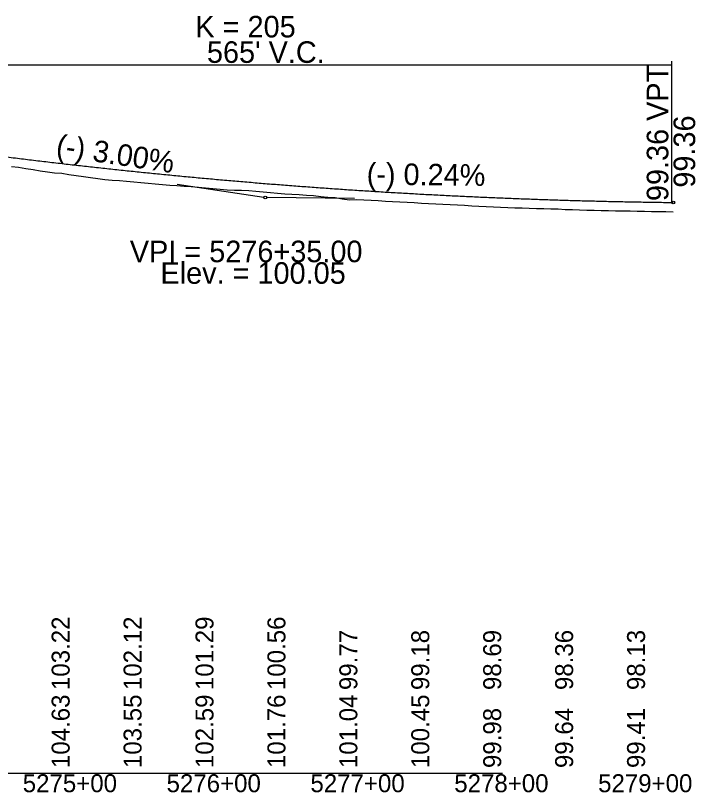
# Model space of a CAD drawing. Extents: x 2121671 to 2169879, y 557274 to 599957.
# Drawn here: x 2157029 to 2157502, y 579173 to 579714 of the extents above; entities that cross this region are included whole.
import ezdxf

# ---------------------------------------------------------------- set-up
doc = ezdxf.new("R2010")
doc.units = 0
for name, color, linetype in [('RD_DDB_GradeTX', 7, 'Continuous'), ('RD_DDB_Profile_EX', 7, 'Continuous'), ('RD_DDB_Profile_Lbl', 7, 'Continuous'), ('RD_DDB_Profile_PR', 7, 'Continuous'), ('RD_DDB_StaTX', 7, 'Continuous'), ('RD_DDB_StripGrade', 7, 'Continuous'), ('RD_DDB_VCLbl', 7, 'Continuous'), ('RD_GPK_Profile_Cell', 7, 'Continuous')]:
    doc.layers.add(name, color=color, linetype=linetype)

msp = doc.modelspace()

# ---------------------------------------------------------------- linework, layer by layer
at = {"layer": 'RD_DDB_GradeTX'}
for p, q in [((2157141.62, 579596.26), (2157201.95, 579587.21)), ((2157264.93, 579586.31), (2157203.93, 579587.05))]:
    msp.add_line(p, q, dxfattribs=at)
for centre in [(2157202.93, 579587.07), (2157486.53, 579583.63)]:
    msp.add_circle(centre, 1, dxfattribs=at)
at = {"layer": 'RD_DDB_Profile_EX'}
for points in [[(2157026.48, 579608.66), (2157031.48, 579608.07), (2157036.48, 579607.26), (2157041.48, 579606.45), (2157046.48, 579605.6), (2157051.48, 579604.83), (2157056.48, 579604.33), (2157061.48, 579603.98), (2157066.48, 579603.12), (2157071.48, 579602.4), (2157076.48, 579601.69), (2157081.48, 579600.99), (2157086.48, 579600.28), (2157091.48, 579599.61), (2157096.48, 579599.22), (2157101.48, 579598.99), (2157106.48, 579598.51), (2157111.48, 579598.06), (2157116.48, 579597.54), (2157121.48, 579597.08), (2157126.48, 579596.62), (2157131.48, 579596.16), (2157136.48, 579595.75), (2157141.48, 579595.36), (2157146.48, 579595), (2157151.48, 579594.65), (2157156.48, 579594.2), (2157161.48, 579593.83), (2157166.48, 579593.4), (2157171.48, 579592.92), (2157176.48, 579592.42), (2157181.48, 579592.07), (2157186.48, 579592.1), (2157191.48, 579591.86), (2157196.48, 579591.4), (2157201.48, 579590.95), (2157206.48, 579590.5), (2157211.48, 579589.99), (2157216.48, 579589.7), (2157221.48, 579589.45)], [(2157221.48, 579589.45), (2157226.48, 579589.11), (2157231.48, 579588.68), (2157236.48, 579588.39), (2157241.48, 579587.88), (2157246.48, 579587.4), (2157251.48, 579586.96), (2157256.48, 579586.09), (2157261.48, 579585.55), (2157266.48, 579585.73), (2157271.48, 579585.51), (2157276.48, 579585.19), (2157281.48, 579584.88), (2157286.48, 579584.59), (2157291.48, 579584.34), (2157296.48, 579584.11), (2157301.48, 579583.86), (2157306.48, 579583.59), (2157311.48, 579583.16), (2157316.48, 579582.81), (2157321.48, 579582.57), (2157326.48, 579582.41), (2157331.48, 579582.23), (2157336.48, 579582.02), (2157341.48, 579581.7), (2157346.48, 579581.33), (2157351.48, 579581.09), (2157356.48, 579580.86), (2157361.48, 579580.61), (2157366.48, 579580.35), (2157371.48, 579580.09), (2157376.48, 579579.95), (2157381.48, 579579.85), (2157386.48, 579579.57), (2157391.48, 579579.47), (2157396.48, 579579.35), (2157401.48, 579579.23), (2157406.48, 579579.11), (2157411.48, 579578.84), (2157416.48, 579578.69), (2157421.48, 579578.47), (2157426.48, 579578.27), (2157431.48, 579578.27), (2157436.48, 579578.15), (2157441.48, 579577.99), (2157446.48, 579577.84), (2157451.48, 579577.73), (2157456.48, 579577.74), (2157461.48, 579577.62), (2157466.48, 579577.51), (2157471.48, 579577.4), (2157476.48, 579577.3), (2157481.48, 579577.26), (2157486.53, 579577.21)]]:
    msp.add_lwpolyline(points, dxfattribs=at)
at = {"layer": 'RD_DDB_Profile_PR'}
msp.add_line((2157485.43, 579583.64), (2157486.53, 579583.63), dxfattribs=at)
msp.add_spline([(2156920.43, 579629.44), (2156931.73, 579627.76), (2156943.03, 579626.11), (2156954.33, 579624.5), (2156965.63, 579622.91), (2156976.93, 579621.36), (2156988.23, 579619.83), (2156999.53, 579618.34), (2157010.83, 579616.88), (2157022.13, 579615.45), (2157033.43, 579614.05), (2157044.73, 579612.68), (2157056.03, 579611.34), (2157067.33, 579610.04), (2157078.63, 579608.76), (2157089.93, 579607.52), (2157101.23, 579606.31), (2157112.53, 579605.13), (2157123.83, 579603.98), (2157135.13, 579602.86), (2157146.43, 579601.77), (2157157.73, 579600.72), (2157169.03, 579599.69), (2157180.33, 579598.7), (2157191.63, 579597.74), (2157202.93, 579596.8), (2157214.23, 579595.9), (2157225.53, 579595.03), (2157236.83, 579594.2), (2157248.13, 579593.39), (2157259.43, 579592.61), (2157270.73, 579591.87), (2157282.03, 579591.16), (2157293.33, 579590.47), (2157304.63, 579589.82), (2157315.93, 579589.2), (2157327.23, 579588.61), (2157338.53, 579588.06), (2157349.83, 579587.53), (2157361.13, 579587.03), (2157372.43, 579586.57), (2157383.73, 579586.14), (2157395.03, 579585.73), (2157406.33, 579585.36), (2157417.63, 579585.02), (2157428.93, 579584.72), (2157440.23, 579584.44), (2157451.53, 579584.19), (2157462.83, 579583.98), (2157474.13, 579583.79), (2157485.43, 579583.64)], degree=3, dxfattribs=at)
at = {"layer": 'RD_DDB_VCLbl'}
for p, q in [((2157485.43, 579681.94), (2157485.43, 579583.64)), ((2156920.43, 579679.44), (2157485.43, 579679.44))]:
    msp.add_line(p, q, dxfattribs=at)
at = {"layer": 'RD_GPK_Profile_Cell'}
msp.add_line((2151067.93, 579186.83), (2157367.93, 579186.83), dxfattribs=at)

# ---------------------------------------------------------------- texts
at = {"layer": 'RD_DDB_GradeTX'}
for s, rotation, p in [('(-) 3.00%', 351.4692, (2157056.9, 579616.21)), ('(-) 0.24%', 359.3056, (2157273.36, 579596.06))]:
    msp.add_text(s, height=15, rotation=rotation, dxfattribs=at).set_placement(p)
at = {"layer": 'RD_DDB_Profile_Lbl'}
msp.add_text('99.36', height=15, rotation=90, dxfattribs=at).set_placement((2157501.77, 579593.92))
for s, p in [('VPI = 5276+35.00', (2157108.78, 579542.07)), ('Elev. = 100.05', (2157130.07, 579527.07))]:
    msp.add_text(s, height=15, dxfattribs=at).set_placement(p)
at = {"layer": 'RD_DDB_StaTX'}
for s, p in [('5275+00', (2157034.32, 579173.53)), ('5276+00', (2157134.32, 579173.53)), ('5277+00', (2157234.32, 579173.53)), ('5278+00', (2157334.32, 579173.53)), ('5279+00', (2157434.32, 579173.53))]:
    msp.add_text(s, height=12.5, dxfattribs=at).set_placement(p)
at = {"layer": 'RD_DDB_StripGrade'}
for s, height, p in [('99.36 VPT', 15, (2157483.12, 579584.58)), ('103.22', 12.5, (2157066.93, 579244.56)), ('102.12', 12.5, (2157116.93, 579244.56)), ('101.29', 12.5, (2157166.93, 579244.56)), ('100.56', 12.5, (2157216.93, 579244.56)), ('99.77', 12.5, (2157266.93, 579244.56)), ('99.18', 12.5, (2157316.93, 579244.56)), ('98.69', 12.5, (2157366.93, 579244.56)), ('98.36', 12.5, (2157416.93, 579244.56)), ('98.13', 12.5, (2157466.93, 579244.56)), ('104.63', 12.5, (2157066.93, 579190.33)), ('103.55', 12.5, (2157116.93, 579190.33)), ('102.59', 12.5, (2157166.93, 579190.33)), ('101.76', 12.5, (2157216.93, 579190.33)), ('101.04', 12.5, (2157266.93, 579190.33)), ('100.45', 12.5, (2157316.93, 579190.33)), ('99.64', 12.5, (2157416.93, 579190.33)), ('99.98', 12.5, (2157366.93, 579190.33)), ('99.41', 12.5, (2157466.93, 579190.33))]:
    msp.add_text(s, height=height, rotation=90, dxfattribs=at).set_placement(p)
at = {"layer": 'RD_DDB_VCLbl'}
for s, p in [('K = 205', (2157154.38, 579698.38)), ("565' V.C.", (2157162.38, 579680.69))]:
    msp.add_text(s, height=15, dxfattribs=at).set_placement(p)

doc.saveas('drawing.dxf')
